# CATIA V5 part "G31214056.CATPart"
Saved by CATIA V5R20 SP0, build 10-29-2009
Part number: G31214056
Revision: 6
Definition: design
Nomenclature: G31214056
Source: made
Description: NOT SPECIFIED
Bounding box of the stored display mesh (mm): x -6 to 56, y -12.31 to 12.31, z -12.5 to 12.5
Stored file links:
  C:\Users\Raffaele\Desktop\3D X SITO CF\BOLEX\23-BUSH REF 312\G31214056.CATPart

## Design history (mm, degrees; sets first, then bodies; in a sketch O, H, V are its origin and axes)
Body1 "MANIFOLD_SOLID_BREP #12383" (main body)
  Solid1: solid without history
Body2 "MANIFOLD_SOLID_BREP #12526"
  Solid2: solid without history
Body3 "MANIFOLD_SOLID_BREP #12669"
  Solid3: solid without history
Body4 "MANIFOLD_SOLID_BREP #12812"
  Solid4: solid without history
Body5 "MANIFOLD_SOLID_BREP #12955"
  Solid5: solid without history
Body6 "MANIFOLD_SOLID_BREP #13100"
  Solid6: solid without history
Body7 "MANIFOLD_SOLID_BREP #13245"
  Solid7: solid without history
Body8 "MANIFOLD_SOLID_BREP #13390"
  Solid8: solid without history
Body9 "MANIFOLD_SOLID_BREP #13535"
  Solid9: solid without history
Body10 "MANIFOLD_SOLID_BREP #13680"
  Solid10: solid without history
Body11 "MANIFOLD_SOLID_BREP #13825"
  Solid11: solid without history
Body12 "MANIFOLD_SOLID_BREP #13970"
  Solid12: solid without history
Body13 "MANIFOLD_SOLID_BREP #14115"
  Solid13: solid without history
Body14 "MANIFOLD_SOLID_BREP #14260"
  Solid14: solid without history
Body15 "MANIFOLD_SOLID_BREP #14405"
  Solid15: solid without history
Body16 "MANIFOLD_SOLID_BREP #14550"
  Solid16: solid without history
Body17 "MANIFOLD_SOLID_BREP #14695"
  Solid17: solid without history
Body18 "MANIFOLD_SOLID_BREP #14840"
  Solid18: solid without history
Body19 "MANIFOLD_SOLID_BREP #14985"
  Solid19: solid without history
Body20 "MANIFOLD_SOLID_BREP #15130"
  Solid20: solid without history
Body21 "MANIFOLD_SOLID_BREP #15275"
  Solid21: solid without history
Body22 "MANIFOLD_SOLID_BREP #15420"
  Solid22: solid without history
Body23 "MANIFOLD_SOLID_BREP #15565"
  Solid23: solid without history
Body24 "MANIFOLD_SOLID_BREP #15710"
  Solid24: solid without history
Body25 "MANIFOLD_SOLID_BREP #15855"
  Solid25: solid without history
Body26 "MANIFOLD_SOLID_BREP #16000"
  Solid26: solid without history
Body27 "MANIFOLD_SOLID_BREP #16145"
  Solid27: solid without history
Body28 "MANIFOLD_SOLID_BREP #16290"
  Solid28: solid without history
Body29 "MANIFOLD_SOLID_BREP #16435"
  Solid29: solid without history
Body30 "MANIFOLD_SOLID_BREP #16580"
  Solid30: solid without history
Body31 "MANIFOLD_SOLID_BREP #16725"
  Solid31: solid without history
Body32 "MANIFOLD_SOLID_BREP #16868"
  Solid32: solid without history
Body33 "MANIFOLD_SOLID_BREP #17011"
  Solid33: solid without history
Body34 "MANIFOLD_SOLID_BREP #17156"
  Solid34: solid without history
Body35 "MANIFOLD_SOLID_BREP #17301"
  Solid35: solid without history
Body36 "MANIFOLD_SOLID_BREP #17446"
  Solid36: solid without history
Body37 "MANIFOLD_SOLID_BREP #17591"
  Solid37: solid without history
Body38 "MANIFOLD_SOLID_BREP #17736"
  Solid38: solid without history
Body39 "MANIFOLD_SOLID_BREP #17881"
  Solid39: solid without history
Body40 "MANIFOLD_SOLID_BREP #18026"
  Solid40: solid without history
Body41 "MANIFOLD_SOLID_BREP #18171"
  Solid41: solid without history
Body42 "MANIFOLD_SOLID_BREP #18316"
  Solid42: solid without history
Body43 "MANIFOLD_SOLID_BREP #18461"
  Solid43: solid without history
Body44 "MANIFOLD_SOLID_BREP #18606"
  Solid44: solid without history
Body45 "MANIFOLD_SOLID_BREP #18751"
  Solid45: solid without history
Body46 "MANIFOLD_SOLID_BREP #18896"
  Solid46: solid without history
Body47 "MANIFOLD_SOLID_BREP #19041"
  Solid47: solid without history
Body48 "MANIFOLD_SOLID_BREP #19186"
  Solid48: solid without history
Body49 "MANIFOLD_SOLID_BREP #19331"
  Solid49: solid without history
Body50 "MANIFOLD_SOLID_BREP #19476"
  Solid50: solid without history
Body51 "MANIFOLD_SOLID_BREP #19621"
  Solid51: solid without history
Body52 "MANIFOLD_SOLID_BREP #19766"
  Solid52: solid without history
Body53 "MANIFOLD_SOLID_BREP #19911"
  Solid53: solid without history
Body54 "MANIFOLD_SOLID_BREP #20056"
  Solid54: solid without history
Body55 "MANIFOLD_SOLID_BREP #20201"
  Solid55: solid without history
Body56 "MANIFOLD_SOLID_BREP #20344"
  Solid56: solid without history
Body57 "MANIFOLD_SOLID_BREP #20487"
  Solid57: solid without history
Body58 "MANIFOLD_SOLID_BREP #20632"
  Solid58: solid without history
Body59 "MANIFOLD_SOLID_BREP #20777"
  Solid59: solid without history
Body60 "MANIFOLD_SOLID_BREP #20922"
  Solid60: solid without history
Body61 "MANIFOLD_SOLID_BREP #21067"
  Solid61: solid without history
Body62 "MANIFOLD_SOLID_BREP #21212"
  Solid62: solid without history
Body63 "MANIFOLD_SOLID_BREP #21357"
  Solid63: solid without history
Body64 "MANIFOLD_SOLID_BREP #21500"
  Solid64: solid without history
Body65 "MANIFOLD_SOLID_BREP #21643"
  Solid65: solid without history
Body66 "MANIFOLD_SOLID_BREP #21788"
  Solid66: solid without history
Body67 "MANIFOLD_SOLID_BREP #21933"
  Solid67: solid without history
Body68 "MANIFOLD_SOLID_BREP #22078"
  Solid68: solid without history
Body69 "MANIFOLD_SOLID_BREP #22223"
  Solid69: solid without history
Body70 "MANIFOLD_SOLID_BREP #22368"
  Solid70: solid without history
Body71 "MANIFOLD_SOLID_BREP #22513"
  Solid71: solid without history
Body72 "MANIFOLD_SOLID_BREP #22658"
  Solid72: solid without history
Body73 "MANIFOLD_SOLID_BREP #22803"
  Solid73: solid without history
Body74 "MANIFOLD_SOLID_BREP #22948"
  Solid74: solid without history
Body75 "MANIFOLD_SOLID_BREP #23093"
  Solid75: solid without history
Body76 "MANIFOLD_SOLID_BREP #23238"
  Solid76: solid without history
Body77 "MANIFOLD_SOLID_BREP #23383"
  Solid77: solid without history
Body78 "MANIFOLD_SOLID_BREP #23528"
  Solid78: solid without history
Body79 "MANIFOLD_SOLID_BREP #23673"
  Solid79: solid without history
Body80 "MANIFOLD_SOLID_BREP #23818"
  Solid80: solid without history
Body81 "MANIFOLD_SOLID_BREP #23963"
  Solid81: solid without history
Body82 "MANIFOLD_SOLID_BREP #24108"
  Solid82: solid without history
Body83 "MANIFOLD_SOLID_BREP #24253"
  Solid83: solid without history
Body84 "MANIFOLD_SOLID_BREP #24398"
  Solid84: solid without history
Body85 "MANIFOLD_SOLID_BREP #24543"
  Solid85: solid without history
Body86 "MANIFOLD_SOLID_BREP #24688"
  Solid86: solid without history
Body87 "MANIFOLD_SOLID_BREP #24833"
  Solid87: solid without history
Body88 "MANIFOLD_SOLID_BREP #24976"
  Solid88: solid without history
Body89 "MANIFOLD_SOLID_BREP #25119"
  Solid89: solid without history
